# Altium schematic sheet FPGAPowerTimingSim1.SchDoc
size B; PageSetup: Record=PageOptions|CenterHorizontal=True|CenterVertical=True|PrintScale=1.12|XCorrection=1.00|YCorrection=1.00|PrintKind=0|BorderSize=5000000|LeftOffset=0|BottomOffset=0|Orientation=2|PaperLength=1000|PaperWidth=1000|Scale=100|PaperSource=7|PrintQuality=-4|MediaType=1|DitherType=10|PaperKind=Tabloid|PrintScaleMode=1
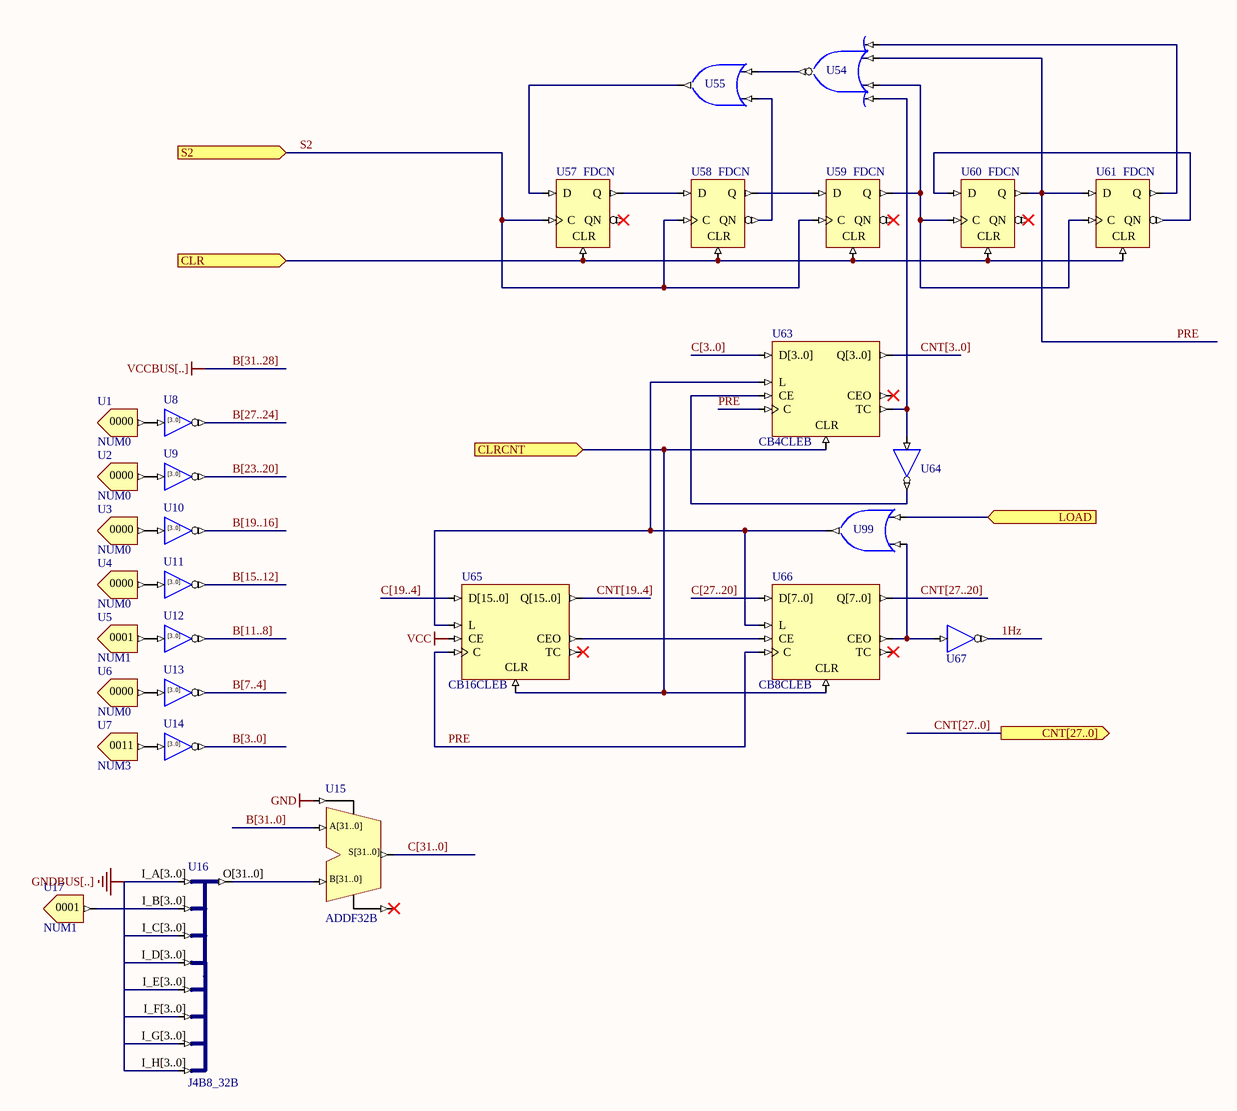
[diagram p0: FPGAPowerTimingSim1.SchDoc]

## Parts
U1  NUM0
U2  NUM0
U3  NUM0
U4  NUM0
U5  NUM1
U6  NUM0
U7  NUM3
U8  INV4B  (value not drawn)
U9  INV4B  (value not drawn)
U10  INV4B  (value not drawn)
U11  INV4B  (value not drawn)
U12  INV4B  (value not drawn)
U13  INV4B  (value not drawn)
U14  INV4B  (value not drawn)
U15  ADDF32B
U16  J4B8_32B
U17  NUM1
U54  NOR4S  (value not drawn)
U55  OR2S  (value not drawn)
U57  FDCN
U58  FDCN
U59  FDCN
U60  FDCN
U61  FDCN
U63  CB4CLEB
U64  INV  (value not drawn)
U65  CB16CLEB
U66  CB8CLEB
U67  INV  (value not drawn)
U99  OR2S  (value not drawn)

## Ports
CLR (in), CLRCNT (in), CNT[27..0] (out), LOAD (in), S2 (in)

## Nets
GND: U15.CI
VCC: U65.CE
1Hz: U67.O
CLR: U57.CLR U58.CLR U59.CLR U60.CLR U61.CLR ; port CLR
CLRCNT: U63.CLR U65.CLR U66.CLR ; port CLRCNT
LOAD: U99.I0 ; port LOAD
PRE: U54.I1 U60.Q U61.D U63.C U65.C U66.C
S2: U57.C U58.C U59.C ; port S2
NetU1_O[3..0]: U1.O[3..0] U8.I[3..0]
NetU2_O[3..0]: U2.O[3..0] U9.I[3..0]
NetU3_O[3..0]: U3.O[3..0] U10.I[3..0]
NetU4_O[3..0]: U4.O[3..0] U11.I[3..0]
NetU5_O[3..0]: U5.O[3..0] U12.I[3..0]
NetU6_O[3..0]: U6.O[3..0] U13.I[3..0]
NetU7_O[3..0]: U7.O[3..0] U14.I[3..0]
NetU54_I0: U54.I0 U61.Q
NetU54_I2: U54.I2 U59.Q U60.C U61.C
NetU54_I3: U54.I3 U63.TC U64.I
NetU54_O: U54.O U55.I0
NetU55_I1: U55.I1 U58.QN
NetU55_O: U55.O U57.D
NetU57_Q: U57.Q U58.D
NetU58_Q: U58.Q U59.D
NetU60_D: U60.D U61.QN
NetU63_CE: U63.CE U64.O
NetU63_L: U63.L U65.L U66.L U99.O
NetU65_CEO: U65.CEO U66.CE
NetU66_CEO: U66.CEO U67.I U99.I1

Not connected (* = marked no-connect by the designer): U8 O[3..0]; U9 O[3..0]; U10 O[3..0]; U11 O[3..0]; U12 O[3..0]; U13 O[3..0]; U14 O[3..0]; U15 A[31..0] B[31..0] CO* S[31..0]; U16 I_A[3..0] I_B[3..0] I_C[3..0] I_D[3..0] I_E[3..0] I_F[3..0] I_G[3..0] I_H[3..0] O[31..0]; U17 O[3..0]; U57 QN*; U59 QN*; U60 QN*; U63 CEO* D[3..0] Q[3..0]; U65 D[15..0] Q[15..0] TC*; U66 D[7..0] Q[7..0] TC*

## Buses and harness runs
bus B[3..0]
bus B[7..4]
bus B[11..8]
bus B[15..12]
bus B[19..16]
bus B[23..20]
bus B[27..24]
bus B[31..0]
bus B[31..28]
bus C[3..0]
bus C[19..4]
bus C[27..20]
bus C[31..0]
bus CNT[3..0]
bus CNT[19..4]
bus CNT[27..0] = port CNT[27..0]
bus CNT[27..20]

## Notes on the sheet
- Labels drawn without touching a wire or pin: GNDBUS[..], VCCBUS[..]

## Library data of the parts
U1-U4 U6 = NUM0: Number Connector 0; FunctionalClass: Numeric Connector; SubClass: 0; PortSize: 4; PortStyle: Bus Version; ArchiveName: GENERIC; VHDLIB_SIM: GENERIC_LIB
U5 U17 = NUM1: Number Connector 1; FunctionalClass: Numeric Connector; SubClass: 1; PortSize: 4; PortStyle: Bus Version; ArchiveName: GENERIC; VHDLIB_SIM: GENERIC_LIB
U7 = NUM3: Number Connector 3; FunctionalClass: Numeric Connector; SubClass: 3; PortSize: 4; PortStyle: Bus Version; ArchiveName: GENERIC; VHDLIB_SIM: GENERIC_LIB
U8-U14 = INV4B: 4-Bit Inverter, Bus Version; FunctionalClass: Logic Primitive; SubClass: INV; PortSize: 4; ArchiveName: GENERIC; VHDLIB_SIM: GENERIC_LIB
U15 = ADDF32B: 32-Bit Cascadable Unsigned Binary Full Adder, Bus Version; FunctionalClass: Arithmetic Function; SubClass: ADDF; PortSize: 32; ArchiveName: GENERIC; VHDLIB_SIM: GENERIC_LIB
U16 = J4B8_32B: 8 x 4-Bit input bus to 1 x 32-bit output bus; FunctionalClass: Bus Joiner; PortSize: 4; ArchiveName: GENERIC; VHDLIB_SIM: GENERIC_LIB
U54 = NOR4S: 4-Input NOR Gate, Single Pin Version; XilinxEquivalent: NOR4; FunctionalClass: Logic Primitive; PortSize: 4; ArchiveName: GENERIC; VHDLIB_SIM: GENERIC_LIB
U55 U99 = OR2S: 2-Input OR Gate, Single Pin Version; XilinxEquivalent: OR2; FunctionalClass: Logic Primitive; PortSize: 2; ArchiveName: GENERIC; VHDLIB_SIM: GENERIC_LIB
U57-U61 = FDCN: D-Type Flip-Flop with Asynchronous Clear and Inverted and Non-Inverted Outputs; SubClass: FD; ClockTrigger: Rising; ArchiveName: GENERIC; VHDLIB_SIM: GENERIC_LIB
U63 = CB4CLEB: 4-Bit Loadable Cascadable Binary Counter with Clock Enable and Asynchronous Clear, Bus Version; ClockTrigger: Rising; Enable: High; Loadable: True; PortSize: 4; ArchiveName: GENERIC; VHDLIB_SIM: GENERIC_LIB
U64 U67 = INV: Inverter; FunctionalClass: Logic Primitive; ArchiveName: GENERIC; VHDLIB_SIM: GENERIC_LIB
U65 = CB16CLEB: 16-Bit Loadable Cascadable Binary Counters with Clock Enable and Asynchronous Clear, Bus Version; ClockTrigger: Rising; Enable: High; Loadable: True; PortSize: 16; ArchiveName: GENERIC; VHDLIB_SIM: GENERIC_LIB
U66 = CB8CLEB: 8-Bit Loadable Cascadable Binary Counter with Clock Enable and Asynchronous Clear, Bus Version; XilinxEquivalent: CB8CLE; ClockTrigger: Rising; Enable: High; Loadable: True; PortSize: 8; ArchiveName: GENERIC; VHDLIB_SIM: GENERIC_LIB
